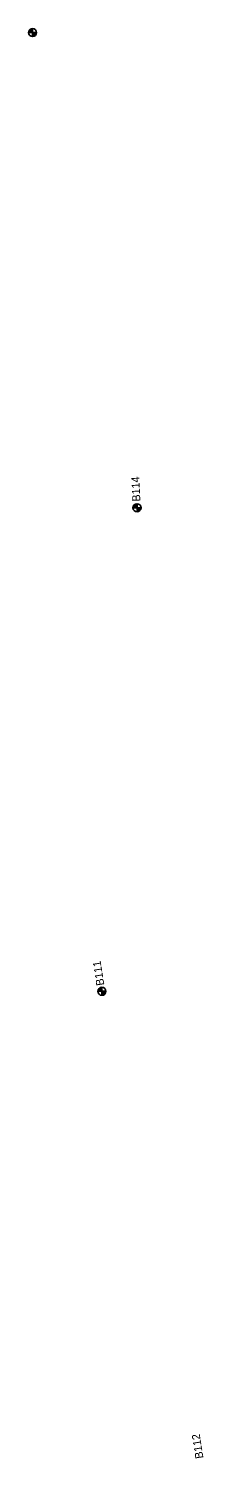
# Model space of a CAD drawing. Extents: x 335726 to 369746, y 119154 to 200788.
# Drawn here: x 355181 to 355399, y 189604 to 191390 of the extents above; entities that cross this region are included whole.
import ezdxf

# ---------------------------------------------------------------- set-up
doc = ezdxf.new("R2010")
doc.units = 0
doc.layers.add('E_SOIL_BORE1 [KAPUR_CADDS_LEVELS]', color=7, linetype='Continuous')
doc.layers.add('P_MARK', color=7, linetype='Continuous')

msp = doc.modelspace()

# ---------------------------------------------------------------- linework, layer by layer
at = {"layer": 'P_MARK'}
for p, q in [((355181.3, 191384.7), (355191.3, 191384.7)), ((355186.3, 191389.7), (355186.3, 191379.7)), ((355311.6, 190791.1), (355321.6, 190791.1)), ((355316.6, 190796.1), (355316.6, 190786.1)), ((355267.7, 190187.1), (355277.7, 190187.1)), ((355272.7, 190192.1), (355272.7, 190182.1))]:
    msp.add_line(p, q, dxfattribs=at)
for centre in [(355186.3, 191384.7), (355316.6, 190791.1), (355272.7, 190187.1)]:
    msp.add_circle(centre, 5, dxfattribs=at)
for centre, radius, start, end in [((355186.3, 191384.7), 4.5, 89.9869, 179.9869), ((355186.3, 191384.7), 4, 89.9869, 179.9869), ((355186.3, 191384.7), 3.5, 89.9869, 179.9869), ((355186.3, 191384.7), 3, 89.9869, 179.9869), ((355186.3, 191384.7), 2.5, 89.9869, 179.9869), ((355186.3, 191384.7), 2, 89.9869, 179.9869), ((355186.3, 191384.7), 1.5, 89.9869, 179.9869), ((355186.3, 191384.7), 1, 89.9869, 179.9869), ((355186.3, 191384.7), 0.5, 89.9869, 179.9869), ((355186.3, 191384.7), 4.5, 269.9869, 359.9869), ((355186.3, 191384.7), 4, 269.9869, 359.9869), ((355186.3, 191384.7), 3.5, 269.9869, 359.9869), ((355186.3, 191384.7), 3, 269.9869, 359.9869), ((355186.3, 191384.7), 2.5, 269.9869, 359.9869), ((355186.3, 191384.7), 2, 269.9869, 359.9869), ((355186.3, 191384.7), 1.5, 269.9869, 359.9869), ((355186.3, 191384.7), 1, 269.9869, 359.9869), ((355186.3, 191384.7), 0.5, 269.9869, 359.9869), ((355316.6, 190791.1), 4.5, 89.9869, 179.9869), ((355316.6, 190791.1), 4, 89.9869, 179.9869), ((355316.6, 190791.1), 3.5, 89.9869, 179.9869), ((355316.6, 190791.1), 3, 89.9869, 179.9869), ((355316.6, 190791.1), 2.5, 89.9869, 179.9869), ((355316.6, 190791.1), 2, 89.9869, 179.9869), ((355316.6, 190791.1), 1.5, 89.9869, 179.9869), ((355316.6, 190791.1), 1, 89.9869, 179.9869), ((355316.6, 190791.1), 0.5, 89.9869, 179.9869), ((355316.6, 190791.1), 4.5, 269.9869, 359.9869), ((355316.6, 190791.1), 4, 269.9869, 359.9869), ((355316.6, 190791.1), 3.5, 269.9869, 359.9869), ((355316.6, 190791.1), 3, 269.9869, 359.9869), ((355316.6, 190791.1), 2.5, 269.9869, 359.9869), ((355316.6, 190791.1), 2, 269.9869, 359.9869), ((355316.6, 190791.1), 1.5, 269.9869, 359.9869), ((355316.6, 190791.1), 1, 269.9869, 359.9869), ((355316.6, 190791.1), 0.5, 269.9869, 359.9869), ((355272.7, 190187.1), 4.5, 89.9869, 179.9869), ((355272.7, 190187.1), 4, 89.9869, 179.9869), ((355272.7, 190187.1), 3.5, 89.9869, 179.9869), ((355272.7, 190187.1), 3, 89.9869, 179.9869), ((355272.7, 190187.1), 2.5, 89.9869, 179.9869), ((355272.7, 190187.1), 2, 89.9869, 179.9869), ((355272.7, 190187.1), 1.5, 89.9869, 179.9869), ((355272.7, 190187.1), 1, 89.9869, 179.9869), ((355272.7, 190187.1), 0.5, 89.9869, 179.9869), ((355272.7, 190187.1), 4.5, 269.9869, 359.9869), ((355272.7, 190187.1), 4, 269.9869, 359.9869), ((355272.7, 190187.1), 3.5, 269.9869, 359.9869), ((355272.7, 190187.1), 3, 269.9869, 359.9869), ((355272.7, 190187.1), 2.5, 269.9869, 359.9869), ((355272.7, 190187.1), 2, 269.9869, 359.9869), ((355272.7, 190187.1), 1.5, 269.9869, 359.9869), ((355272.7, 190187.1), 1, 269.9869, 359.9869), ((355272.7, 190187.1), 0.5, 269.9869, 359.9869)]:
    msp.add_arc(centre, radius, start, end, dxfattribs=at)

# ---------------------------------------------------------------- texts
at = {"layer": 'E_SOIL_BORE1 [KAPUR_CADDS_LEVELS]'}
for s, rotation, p in [('B114', 93.0065, (355320.9, 190799.2)), ('B111', 98.957, (355275.9, 190195)), ('B112', 98.957, (355399.6, 189604.1))]:
    msp.add_text(s, height=10, rotation=rotation, dxfattribs=at).set_placement(p)

doc.saveas('drawing.dxf')
